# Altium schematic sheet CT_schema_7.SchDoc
size 287 x 243 mm
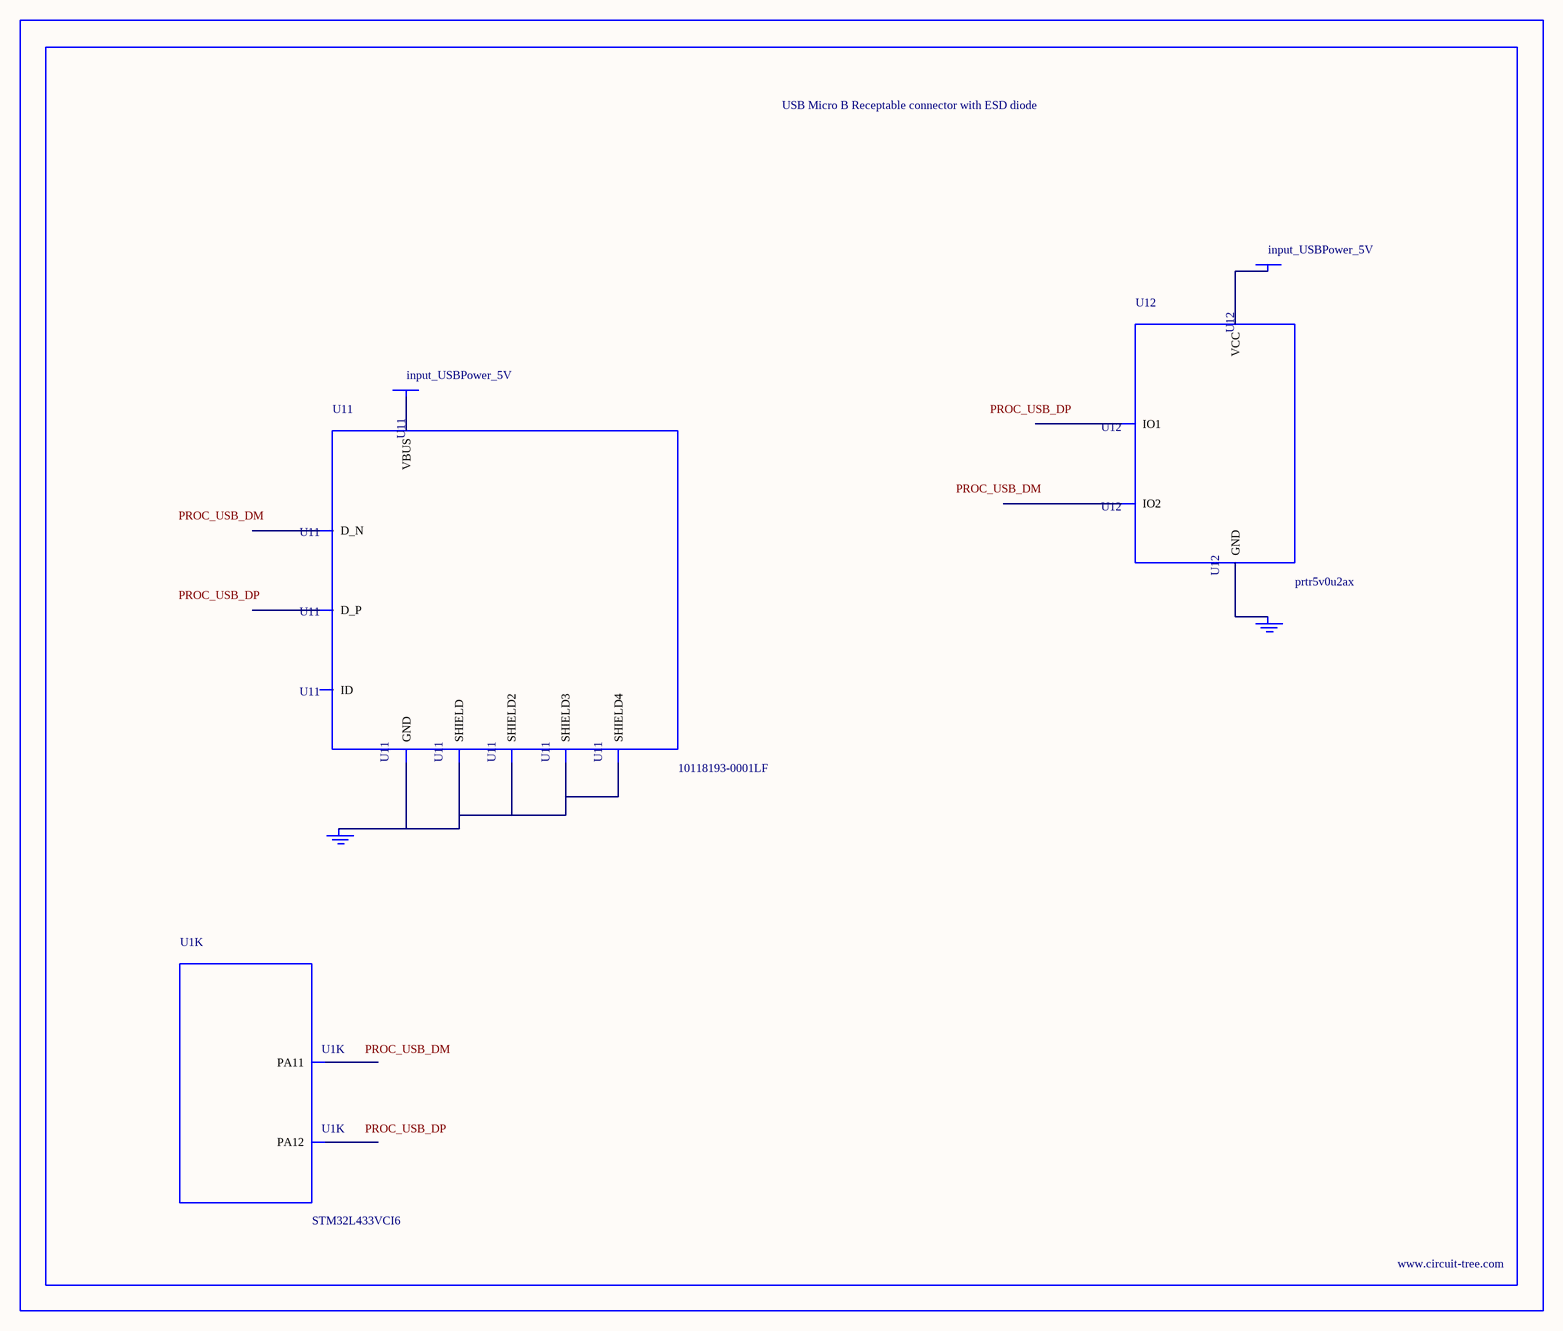
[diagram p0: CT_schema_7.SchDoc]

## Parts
BORDER6  (no value)
GND_INSTANCE_6_0  (no value)
GND_INSTANCE_6_1  (no value)
POWER_INSTANCE_6_0  input_USBPower_5V
POWER_INSTANCE_6_1  input_USBPower_5V
U1  STM32L433VCI6  [UFBGA100]  (part K of 11)
U11  10118193-0001LF  [FCI_10118193-0001LF]
U12  prtr5v0u2ax  [SOT143B]

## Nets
NetGND_INSTANCE_6_0_0: GND_INSTANCE_6_0.0(GND) U11.5(GND) U11.6(SHIELD) U11.7(SHIELD2) U11.8(SHIELD3) U11.9(SHIELD4)
NetGND_INSTANCE_6_1_0: GND_INSTANCE_6_1.0(GND) U12.1(GND)
NetPOWER_INSTANCE_6_0_0: POWER_INSTANCE_6_0.0(PWR) U11.1(VBUS)
NetPOWER_INSTANCE_6_1_0: POWER_INSTANCE_6_1.0(PWR) U12.4(VCC)

Not connected (* = marked no-connect by the designer): U1 A12(PA12) B12(PA11); U11 2(D_N) 3(D_P) 4(ID); U12 2(IO1) 3(IO2)

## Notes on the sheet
- Labels drawn without touching a wire or pin: PROC_USB_DM, PROC_USB_DP

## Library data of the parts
BORDER6 = BORDER_PAGE6
GND_INSTANCE_6_0 GND_INSTANCE_6_1 = GND
POWER_INSTANCE_6_0 POWER_INSTANCE_6_1 = PWR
